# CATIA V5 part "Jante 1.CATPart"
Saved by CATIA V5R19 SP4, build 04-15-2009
Part number: Jantes
Bounding box of the stored display mesh (mm): x -718 to 642, y -244.759 to 244.759, z -244.793 to 244.793
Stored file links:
  G:\EU_thinkMotion\CFAO_2010\MMS_groupe1\MMS_groupe1\OK\rragonneau\rragonneau\Jante 1.CATPart
  F:\Squelette\Deambulateur.CATProduct
  G:\EU_thinkMotion\CFAO_2010\MMS_groupe1\MMS_groupe1\OK\rragonneau\rragonneau\squelette bras 1.CATPart
  G:\EU_thinkMotion\CFAO_2010\MMS_groupe1\MMS_groupe1\OK\rragonneau\rragonneau\squelette de base.CATPart
  G:\EU_thinkMotion\CFAO_2010\MMS_groupe1\MMS_groupe1\OK\rragonneau\rragonneau\squelette jante.CATPart
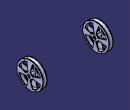
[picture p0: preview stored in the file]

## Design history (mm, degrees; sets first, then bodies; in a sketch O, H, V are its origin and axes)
Parameters
  diam_axe = 30 mm
  diam_jante = 500 mm
  epaisseur_jante = 10 mm
External parameters (linked from other documents)
  `External.diam_moyeu_ext / epaisseur_bras&montant` = 60 mm
  External.epaisseur_pneu = 60 mm
Set1
  Sketch1 on zx-plane, origin (0, 0, 0), H (-1, 0, 0), V (0, 0, 1)
    arc A1 centre (-582, 250) radius 30 from (-611.5507, 244.8275) to (-552.4493, 244.8275) ccw
    point P1 (-582, 250)
    point P2 (-552.4493, 244.8275)
    arc A2 centre (-582, 250) radius 40 from (-613.0861, 224.8275) to (-550.9139, 224.8275) ccw
    point P4 (-550.9139, 224.8275)
    point P5 (-613.0861, 224.8275)
    line L1 (-613.0861, 224.8275) -> (-632, 25)
    point P6 (-632, 25)
    line L2 (-632, 25) -> (-532, 25)
    point P7 (-532, 25)
    point P8 (-621.401, 243.1033)
    point P9 (-642, 0)
    reference projected line E1 (-650, 0) -> (-850, 0) from Line1
    line L3 (-642, 0) -> (-522, 0)
    line L4 (-621.401, 243.1033) -> (-642, 25.4722)
    line L5 (-642, 25.4722) -> (-642, 0)
    point P12 (-642, 0)
    construction line L6 (-611.5507, 244.8275) -> (-725.5336, 244.8275)
    reference projected line E2 (-612, 0) -> (-812, 0) from Line1
    line L7 (-611.5507, 244.8275) -> (-621.401, 243.1033)
    point P14 (-621.401, 243.1033)
    line L8 (-552.4493, 244.8275) -> (-542.599, 243.1033)
    point P15 (-542.599, 243.1033)
    line L9 (-522, 0) -> (-522, 25.4722)
    line L10 (-542.599, 243.1033) -> (-522, 25.4722)
    line L11 (-532, 25) -> (-550.9139, 224.8275)
    construction line L12 (-582, 250) -> (-582, 31.2959)
    reference projected line E3 (-612, 0) -> (-812, 0) from Line1
    construction line L13 (-613.0861, 224.8275) -> (-732.8525, 224.8275)
    axis line L14 (-676.3474, 250) -> (-506.6058, 250)
    reference intersected line E4 through (-582, 0) direction (0, -1) from Plane3
    reference projected line E5 (-582, 0) -> (-582, 47.0542) from Line2
    reference projected line E6 (-582, 0) -> (-582, 47.0542) from Line2
    radius A1 = 30 {= External.epaisseur_pneu /2}
    distance A1 A2 = 10 {= epaisseur_jante}
    distance L2 E1 = 25 {= diam_axe /2+epaisseur_jante}
    length L3 = 120 {= External.epaisseur_pneu *2}
    distance L5 P6 = 10 {= epaisseur_jante}
    distance P5 L4 = 10 {= epaisseur_jante}
    distance L9 P7 = 10 {= epaisseur_jante}
    distance P1 L3 = 250 {= diam_jante /2}
    distance L13 L6 = 20 {= epaisseur_jante *2}
    distance L5 L12 = 60 {= External.epaisseur_pneu}
    horizontal: L2 H, L3 H, L14 H
    vertical: L5 V, L9 V, L12 V
    parallelism: L6 E2, L4 L1, L11 L10
    coincidence: P2 L6, L7 P1, P14 A2, P14 P8, L8 P1, P15 A2, P12 P9, L3 E3, P4 L13, L14 P1, L12 E4, L12 E5, L12 E6
Set2
  Line1: linked copy from another document
  Plane1: linked copy from another document
  Point1: linked copy from another document
  Plane2: linked copy from another document
  Plane3: linked copy from another document
  Line2: linked copy from another document
Body1 (main body)
  Shaft1: profile Sketch1, axis Line1, angle 360
  Sketch2 on Plane1, origin (582, -11.7776, 11.7776), H (0, 1, 0), V (0, 0, 1)
    point P1 (11.7776, -11.7776)
    reference projected point E1 (11.7776, -11.7776) from Point1
    coincidence: P1 E1
  Hole1: placed by Sketch2, at (582, 0, 0) direction (-1, 0, 0), diameter 30 {= diam_axe}, through (limit type 3)
  Mirror1: of the body so far, about Plane2
  Sketch3 on Plane1, origin (582, 0, 0), H (0, 1, 0), V (0, 0, 1)
    arc A1 centre (0, 0) radius 210 from (202.8444, 54.352) to (54.352, 202.8444) ccw
    arc A2 centre (0, 0) radius 60 from (57.9555, 15.5291) to (15.5291, 57.9555) ccw
    line L1 (57.9555, 15.5291) -> (202.8444, 54.352)
    line L2 (54.352, 202.8444) -> (15.5291, 57.9555)
    reference projected point E1 (0, 0) from edge
    reference projected point E2 (0, 0) from Point1
    reference projected point E3 (0, 0) from Point1
    radius A1 = 210 {= diam_jante /2-External.epaisseur_pneu /2-epaisseur_jante}
    distance A2 E1 = 60 {= `External.diam_moyeu_ext / epaisseur_bras&montant`}
    angle L1 H = 15
    angle V L2 = 15
    coincidence: L1 E2, L2 E3
  Pocket1: profile Sketch3, direction (-1, 0, 0), through (limit type 3), opposite side through (limit type 3)
  CircPattern1: of Pocket1, instances 4, angular step 90, axis from Line1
